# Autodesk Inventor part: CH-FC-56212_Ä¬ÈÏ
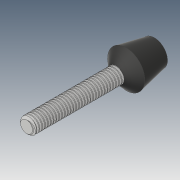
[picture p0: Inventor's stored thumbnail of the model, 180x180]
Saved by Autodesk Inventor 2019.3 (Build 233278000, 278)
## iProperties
Created: 2010-06
Part Number: CH-FC-56212_Ä¬ÈÏ
Material: Ogólny
Document SubType Name: Modeling
Designer: CADENGINEERING4
Density: 1 g/cm^3
Appearance: Domyślna
Author: CADENGINEERING4
Revision Number: ÈÎºÎ
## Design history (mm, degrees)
feature "NONE"
node "Bryła1"
